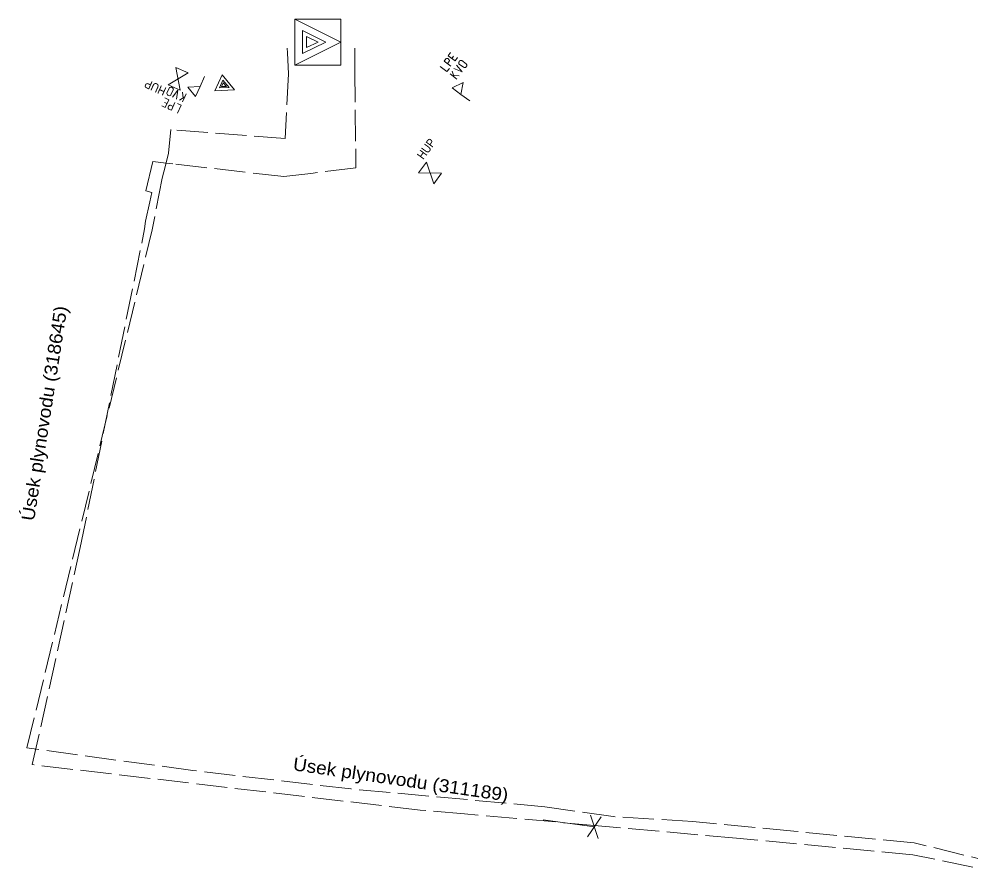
# Model space of a CAD drawing. Extents: x -688140 to -687678, y -1056859 to -1056384.
# Drawn here: x -688129.3 to -688074.2, y -1056685.1 to -1056635.5 of the extents above; entities that cross this region are included whole.
import ezdxf
from ezdxf.enums import TextEntityAlignment as Align

# ---------------------------------------------------------------- set-up
doc = ezdxf.new("R2010")
doc.units = 0
doc.header["$LTSCALE"] = 0.3
doc.linetypes.add('LONG_DASHED', pattern=[7.5, 6, -1.5])
for name, color, linetype, lineweight in [('12', 7, 'Continuous', 13), ('13', 7, 'Continuous', 13), ('25', 7, 'Continuous', 13), ('35', 7, 'LONG_DASHED', 13), ('40', 7, 'LONG_DASHED', 13)]:
    doc.layers.add(name, color=color, linetype=linetype, lineweight=lineweight)
doc.layers.add('15', color=7, linetype='Continuous')

msp = doc.modelspace()

# ---------------------------------------------------------------- linework, layer by layer
at = {"layer": '12'}
for p, q in [((-688119.565, -1056638.628), (-688120.267, -1056638.313)), ((-688120.011, -1056639.623), (-688120.267, -1056638.313)), ((-688120.713, -1056639.308), (-688119.565, -1056638.628)), ((-688118.604, -1056638.836), (-688118.861, -1056639.411)), ((-688120.783, -1056639.791), (-688120.656, -1056639.508)), ((-688120.011, -1056639.623), (-688120.713, -1056639.308)), ((-688120.428, -1056639.61), (-688120.554, -1056639.893)), ((-688119.752, -1056640.01), (-688120.061, -1056640.211)), ((-688119.852, -1056640.086), (-688119.885, -1056639.742)), ((-688119.879, -1056640.293), (-688119.675, -1056639.836)), ((-688120.925, -1056640.33), (-688120.779, -1056640.395)), ((-688120.573, -1056640.498), (-688120.427, -1056640.563))]:
    msp.add_line(p, q, dxfattribs=at)
for points in [[(-688118.009, -1056639.657), (-688116.877, -1056639.611), (-688117.596, -1056638.736)], [(-688117.75, -1056639.494), (-688117.182, -1056639.475), (-688117.546, -1056639.038)], [(-688118.861, -1056639.411), (-688119.567, -1056639.447), (-688119.122, -1056639.996)], [(-688117.619, -1056639.41), (-688117.333, -1056639.407), (-688117.521, -1056639.191)]]:
    msp.add_lwpolyline(points, close=True, dxfattribs=at)
for points in [[(-688120.428, -1056639.61), (-688120.412, -1056639.573), (-688120.422, -1056639.547), (-688120.446, -1056639.503), (-688120.478, -1056639.477), (-688120.524, -1056639.457), (-688120.551, -1056639.445), (-688120.604, -1056639.465), (-688120.631, -1056639.475), (-688120.656, -1056639.508)], [(-688120.226, -1056640.138), (-688120.15, -1056639.624), (-688120.463, -1056640.032)], [(-688121.085, -1056640.542), (-688120.885, -1056640.632), (-688120.681, -1056640.176), (-688120.9, -1056640.078)], [(-688120.554, -1056639.893), (-688120.567, -1056639.92), (-688120.597, -1056639.939), (-688120.646, -1056639.95), (-688120.682, -1056639.934), (-688120.728, -1056639.914), (-688120.755, -1056639.901), (-688120.776, -1056639.849), (-688120.786, -1056639.822), (-688120.783, -1056639.791)], [(-688120.675, -1056640.726), (-688120.712, -1056640.687), (-688120.716, -1056640.598), (-688120.7, -1056640.561), (-688120.626, -1056640.496), (-688120.573, -1056640.498)], [(-688120.325, -1056640.335), (-688120.528, -1056640.791), (-688120.675, -1056640.726)], [(-688120.172, -1056640.95), (-688119.969, -1056640.494), (-688120.179, -1056640.4)]]:
    msp.add_lwpolyline(points, dxfattribs=at)
at = {"layer": '13'}
for p, q in [((-688104.44, -1056637.961), (-688104.536, -1056638.089)), ((-688104.198, -1056637.654), (-688104.294, -1056637.782)), ((-688103.704, -1056637.912), (-688103.456, -1056638.097)), ((-688104.145, -1056638.868), (-688104.273, -1056638.522)), ((-688103.606, -1056638.297), (-688103.854, -1056638.112)), ((-688104.393, -1056638.682), (-688103.993, -1056638.982)), ((-688104.197, -1056638.754), (-688103.855, -1056638.798)), ((-688103.253, -1056640.247), (-688103.757, -1056639.87)), ((-688106.217, -1056644.408), (-688105.763, -1056643.787)), ((-688105.763, -1056643.787), (-688105.337, -1056645.051)), ((-688106.217, -1056644.408), (-688104.883, -1056644.43)), ((-688105.337, -1056645.051), (-688104.883, -1056644.43)), ((-688096.43, -1056682.877), (-688095.632, -1056681.705)), ((-688095.806, -1056682.963), (-688096.256, -1056681.619))]:
    msp.add_line(p, q, dxfattribs=at)
for points in [[(-688113.377, -1056638.171), (-688110.711, -1056636.838), (-688113.377, -1056635.505)], [(-688113.377, -1056638.171), (-688110.711, -1056638.171), (-688110.711, -1056635.505), (-688113.377, -1056635.505)], [(-688112.937, -1056637.499), (-688111.593, -1056636.838), (-688112.937, -1056636.177)], [(-688112.705, -1056637.163), (-688112.033, -1056636.838), (-688112.705, -1056636.513)], [(-688103.757, -1056639.87), (-688103.636, -1056639.173), (-688104.27, -1056639.486)]]:
    msp.add_lwpolyline(points, close=True, dxfattribs=at)
for points in [[(-688104.336, -1056638.238), (-688104.736, -1056637.939), (-688104.64, -1056637.811)], [(-688104.64, -1056637.811), (-688104.594, -1056637.783), (-688104.506, -1056637.799), (-688104.474, -1056637.823), (-688104.426, -1056637.909), (-688104.44, -1056637.961)], [(-688104.371, -1056637.45), (-688104.502, -1056637.627), (-688104.102, -1056637.926), (-688103.958, -1056637.734)], [(-688103.854, -1056638.112), (-688103.878, -1056638.094), (-688103.89, -1056638.06), (-688103.89, -1056638.01), (-688103.866, -1056637.978), (-688103.836, -1056637.938), (-688103.818, -1056637.914), (-688103.762, -1056637.906), (-688103.734, -1056637.902), (-688103.704, -1056637.912)], [(-688104.97, -1056638.251), (-688104.569, -1056638.551), (-688104.431, -1056638.367)], [(-688104.165, -1056638.378), (-688103.681, -1056638.566), (-688104.01, -1056638.17)], [(-688103.606, -1056638.297), (-688103.574, -1056638.321), (-688103.546, -1056638.317), (-688103.498, -1056638.303), (-688103.466, -1056638.277), (-688103.436, -1056638.237), (-688103.418, -1056638.213), (-688103.426, -1056638.157), (-688103.43, -1056638.129), (-688103.456, -1056638.097)]]:
    msp.add_lwpolyline(points, dxfattribs=at)
at = {"layer": '25'}
msp.add_line((-688096.031, -1056682.291), (-688099.004, -1056681.881), dxfattribs=at)
at = {"layer": '35'}
msp.add_line((-688113.809, -1056637.465), (-688113.822, -1056637.198), dxfattribs=at)
for points in [[(-688113.809, -1056637.465), (-688113.75, -1056638.67), (-688113.93, -1056642.43), (-688120.56, -1056641.91), (-688120.69, -1056643.27), (-688120.87, -1056643.99), (-688121.07, -1056644.73), (-688121.64, -1056647.72)], [(-688068.396, -1056668.333), (-688069.437, -1056667.945), (-688070.688, -1056675.841), (-688072.45, -1056684.47), (-688077.51, -1056683.22), (-688084.482, -1056682.546), (-688090.337, -1056681.98), (-688094.945, -1056681.697), (-688098.905, -1056681.128), (-688110.126, -1056680.1), (-688119.276, -1056679.031), (-688128.89, -1056677.72), (-688121.64, -1056647.72)]]:
    msp.add_lwpolyline(points, dxfattribs=at)
at = {"layer": '40'}
msp.add_line((-688109.902, -1056637.52), (-688109.9, -1056637.192), dxfattribs=at)
for points in [[(-688109.902, -1056637.52), (-688109.91, -1056638.52), (-688109.84, -1056644.13), (-688112.46, -1056644.444), (-688114.01, -1056644.63), (-688120.443, -1056643.894), (-688120.835, -1056643.849), (-688121.61, -1056643.76), (-688122.01, -1056645.46), (-688121.66, -1056645.55), (-688121.78, -1056646.09), (-688122.02, -1056647.21), (-688122.08, -1056647.65)], [(-688069.58, -1056675.4), (-688071.91, -1056685.08), (-688077.6, -1056683.91), (-688087.804, -1056682.95), (-688096.034, -1056682.213), (-688103.554, -1056681.539), (-688106.12, -1056681.32), (-688128.58, -1056678.69), (-688125.804, -1056666.123), (-688122.08, -1056647.65)]]:
    msp.add_lwpolyline(points, dxfattribs=at)

# ---------------------------------------------------------------- texts
at = {"layer": '12', "width": 0.9}
msp.add_text('HUP', height=0.5, rotation=155.822, dxfattribs=at).set_placement((-688121.359, -1056639.243), align=Align.CENTER)
at = {"layer": '13', "width": 0.9}
msp.add_text('HUP', height=0.5, rotation=53.818, dxfattribs=at).set_placement((-688105.565, -1056643.17), align=Align.CENTER)
at = {"layer": '15', "width": 1.1}
for s, rotation, p in [('Úsek plynovodu (318645)', 81.143, (-688128.48, -1056664.61)), ('Úsek plynovodu (311189)', 351.705, (-688113.52, -1056679.01))]:
    msp.add_text(s, height=0.75, rotation=rotation, dxfattribs=at).set_placement(p)

doc.saveas('drawing.dxf')
